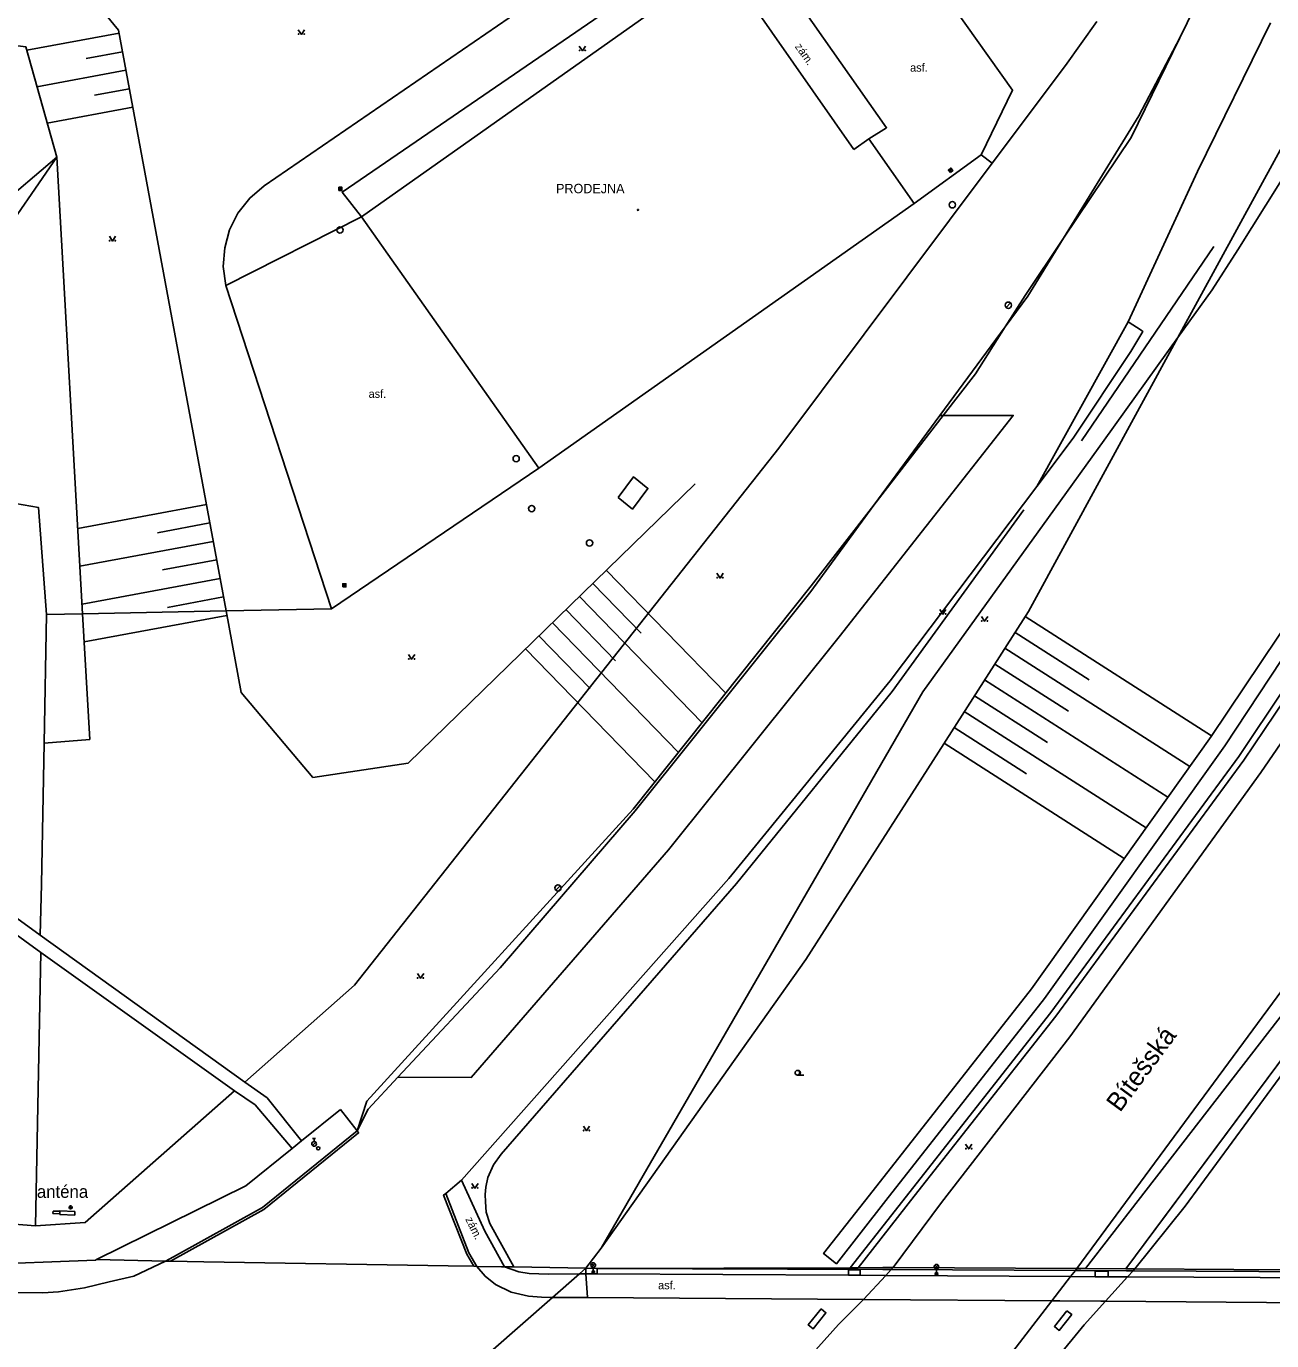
# Model space of a CAD drawing. Extents: x -602419 to -601554, y -1162937 to -1162362.
# Drawn here: x -601838.6 to -601739.3, y -1162718.7 to -1162613.9 of the extents above; entities that cross this region are included whole.
import ezdxf

# ---------------------------------------------------------------- set-up
doc = ezdxf.new("R2010")
doc.units = 0
doc.layers.add('Podklad', color=7, linetype='Continuous')

msp = doc.modelspace()

# ---------------------------------------------------------------- linework, layer by layer
at = {"layer": 'Podklad'}
for p, q in [((-601764.9776, -1162625.4581), (-601764.7824, -1162625.3019)), ((-601813.675, -1162626.86), (-601813.425, -1162626.86)), ((-601760.447, -1162636.3165), (-601760.0935, -1162635.963)), ((-601813.365, -1162658.48), (-601813.115, -1162658.48)), ((-601796.377, -1162682.7965), (-601796.0235, -1162682.443)), ((-601777.1, -1162697.5475), (-601776.6, -1162697.5475)), ((-601815.779, -1162703.176), (-601815.514, -1162702.911)), ((-601815.775, -1162702.6025), (-601815.525, -1162702.6025)), ((-601815.65, -1162702.8525), (-601815.65, -1162702.6025)), ((-601793.5125, -1162712.84), (-601793.2475, -1162712.575)), ((-601793.5125, -1162712.575), (-601793.2475, -1162712.84)), ((-601793.38, -1162712.895), (-601793.38, -1162713.27)), ((-601766.1425, -1162712.97), (-601765.8775, -1162712.705)), ((-601766.1425, -1162712.705), (-601765.8775, -1162712.97)), ((-601766.01, -1162713.025), (-601766.01, -1162713.4))]:
    msp.add_line(p, q, dxfattribs=at)
for points in [[(-601808.15, -1162672.6599), (-601815.75, -1162673.8), (-601821.46, -1162667.02), (-601822.6642, -1162660.5227), (-601831.25, -1162614.2), (-601835.42, -1162609.1), (-601841.14, -1162606.25), (-601856.39, -1162605.09), (-601882.54, -1162586.09)], [(-601811.44, -1162699.63), (-601790.2, -1162676.34), (-601776.01, -1162658.53), (-601771.0161, -1162652.0886), (-601765.466, -1162644.9297), (-601762.9, -1162641.62), (-601760.5218, -1162637.8699), (-601758.93, -1162635.36), (-601755.8662, -1162630.788), (-601750.48, -1162622.75), (-601746.602, -1162614.8054), (-601737.73, -1162596.63)], [(-601767.78, -1162628.02), (-601762.44, -1162624.15), (-601759.94, -1162619), (-601772.06, -1162601.92)], [(-601785.2, -1162602.9699), (-601819.62, -1162626.61)], [(-601884.69, -1162606.27), (-601871.19, -1162607.53), (-601858.53, -1162613.06), (-601840.5739, -1162615.291), (-601838.65, -1162615.53), (-601836.18, -1162624.34)], [(-601811.86, -1162629.08), (-601813.4099, -1162627.12), (-601783.04, -1162606.31)], [(-601780.9099, -1162606.4099), (-601769.99, -1162621.98), (-601771.4, -1162622.88)], [(-601811.86, -1162629.08), (-601781.92, -1162607.94)], [(-601780.69, -1162612.1599), (-601772.59, -1162623.71)], [(-601816.9099, -1162614.165), (-601816.6599, -1162614.54), (-601816.4099, -1162614.165)], [(-601803.88, -1162705.94), (-601782.56, -1162681.86), (-601769.7, -1162666.09), (-601758, -1162650.59), (-601755.1, -1162646.75), (-601750.51, -1162639.84), (-601749.54, -1162638.24), (-601749.69, -1162638.14), (-601750.71, -1162637.46), (-601745.19, -1162625.47), (-601739.36, -1162613.62)], [(-601761.56, -1162624.8199), (-601755.72, -1162617.0199), (-601753.21, -1162613.52)], [(-601831.2, -1162614.45), (-601838.57, -1162615.81)], [(-601794.5, -1162615.465), (-601794.25, -1162615.84), (-601794, -1162615.465)], [(-601771.0161, -1162652.0886), (-601765.732, -1162644.93), (-601760.5218, -1162637.8699), (-601758.717, -1162635.4249), (-601755.8662, -1162630.788), (-601749.8638, -1162621.0248), (-601746.602, -1162614.8054)], [(-601746.75, -1162638.71), (-601734.06, -1162615.46)], [(-601830.93, -1162615.92), (-601833.82, -1162616.46)], [(-601757.4, -1162691.44), (-601770.04, -1162707.55), (-601773.99, -1162712.59), (-601775.01, -1162711.79), (-601771.06, -1162706.75), (-601758.44, -1162690.6599), (-601744.1, -1162670.55), (-601729.44, -1162648.7), (-601716.39, -1162627.23), (-601716.71, -1162624), (-601732.24, -1162616.35)], [(-601746.75, -1162638.71), (-601744.01, -1162634.91), (-601741.98, -1162631.71), (-601738.61, -1162626.39), (-601734.96, -1162620.65), (-601732.34, -1162616.52), (-601732.24, -1162616.35)], [(-601830.6599, -1162617.4), (-601837.76, -1162618.71)], [(-601830.38, -1162618.87), (-601833.17, -1162619.39)], [(-601830.11, -1162620.35), (-601836.94, -1162621.61)], [(-601772.59, -1162623.71), (-601771.4, -1162622.88)], [(-601771.4, -1162622.88), (-601767.78, -1162628.02)], [(-601836.18, -1162624.34), (-601841.0524, -1162631.4107), (-601845.8, -1162638.3), (-601865.86, -1162636.4)], [(-601836.18, -1162624.34), (-601841.0118, -1162628.4378), (-601848.1599, -1162634.5), (-601865.49, -1162632.86)], [(-601836.18, -1162624.34), (-601834.111, -1162660.7441), (-601833.54, -1162670.79)], [(-601821.168, -1162698.102), (-601812.43, -1162690.3699), (-601778.57, -1162647.5299), (-601761.56, -1162624.8199)], [(-601761.56, -1162624.8199), (-601762.44, -1162624.15)], [(-601819.62, -1162626.61), (-601820.78, -1162627.6), (-601821.73, -1162628.79), (-601822.4, -1162630.12), (-601822.78, -1162631.56), (-601822.89, -1162633.04), (-601822.68, -1162634.58)], [(-601754.81, -1162712.98), (-601750.93, -1162707.7199), (-601730.62, -1162680.1599), (-601712.05, -1162651.99), (-601703.56, -1162637.96), (-601697.14, -1162626.52)], [(-601767.78, -1162628.02), (-601797.73, -1162649.15)], [(-601811.86, -1162629.08), (-601822.68, -1162634.58)], [(-601797.73, -1162649.15), (-601811.86, -1162629.08)], [(-601716.64, -1162629.79), (-601728.48, -1162649.29), (-601743.02, -1162671.28), (-601757.4, -1162691.44)], [(-601831.98, -1162630.645), (-601831.73, -1162631.02), (-601831.48, -1162630.645)], [(-601772.89, -1162712.9099), (-601756.9, -1162692.56), (-601741.89, -1162672.13), (-601727.1599, -1162650.1), (-601721.39, -1162640.75), (-601715.45, -1162630.9)], [(-601714.93, -1162631.2199), (-601720.98, -1162641.02), (-601726.65, -1162650.42), (-601741.48, -1162672.42), (-601756.5, -1162692.86), (-601767.78, -1162707.21), (-601772.25, -1162712.9099)], [(-601754.43, -1162646.96), (-601743.88, -1162631.45)], [(-601822.68, -1162634.58), (-601814.27, -1162660.36), (-601797.73, -1162649.15)], [(-601758, -1162650.59), (-601750.71, -1162637.46)], [(-601793.98, -1162712.96), (-601792.76, -1162711.36), (-601789.4, -1162705.55), (-601779.84, -1162689.02), (-601774.55, -1162679.88), (-601767.1, -1162666.99), (-601757.08, -1162653.06), (-601752.64, -1162646.9), (-601746.75, -1162638.71)], [(-601793.98, -1162712.96), (-601792.76, -1162711.36), (-601789.4, -1162705.55), (-601779.84, -1162689.02), (-601774.55, -1162679.88), (-601767.1, -1162666.99), (-601757.08, -1162653.06), (-601752.64, -1162646.9), (-601746.75, -1162638.71)], [(-601792.76, -1162711.36), (-601776.44, -1162688.33), (-601758.67, -1162660.56), (-601746.75, -1162638.71)], [(-601765.732, -1162644.93), (-601765.466, -1162644.9297), (-601759.891, -1162644.924), (-601773.759, -1162662.6), (-601787.369, -1162679.592), (-601803.119, -1162697.739), (-601808.958, -1162697.726), (-601811.331, -1162700.27), (-601812.2199, -1162702)], [(-601791.4099, -1162651.48), (-601790.18, -1162649.84), (-601789.03, -1162650.75), (-601790.26, -1162652.4), (-601791.4099, -1162651.48)], [(-601808.15, -1162672.6599), (-601785.26, -1162650.4)], [(-601836.99, -1162660.7999), (-601837.63, -1162652.2799), (-601841.33, -1162651.6499)], [(-601824.24, -1162652.04), (-601834.5, -1162653.94)], [(-601808.958, -1162697.726), (-601800.81, -1162688.99), (-601790.031, -1162676.477), (-601776.028, -1162658.975), (-601771.0161, -1162652.0886)], [(-601800.73, -1162703.85), (-601781.96, -1162682.27), (-601769.54, -1162666.94), (-601759.04, -1162652.4699)], [(-601823.96, -1162653.51), (-601828.14, -1162654.29)], [(-601823.69, -1162654.99), (-601834.33, -1162656.96)], [(-601823.42, -1162656.46), (-601827.75, -1162657.26)], [(-601792.34, -1162657.29), (-601782.82, -1162667.08)], [(-601711.36, -1162657), (-601711.57, -1162657.34), (-601720.41, -1162670.93), (-601728.96, -1162683.45), (-601736.3, -1162693.37), (-601750.9, -1162713)], [(-601711.03, -1162657.22), (-601727.42, -1162682.48), (-601746.1599, -1162708), (-601750.2, -1162713.01)], [(-601823.14, -1162657.94), (-601834.15, -1162659.98)], [(-601793.42, -1162658.33), (-601789.55, -1162662.3)], [(-601783.52, -1162657.525), (-601783.27, -1162657.9), (-601783.02, -1162657.525)], [(-601822.87, -1162659.4099), (-601827.35, -1162660.24)], [(-601794.49, -1162659.38), (-601784.7, -1162669.44)], [(-601836.99, -1162660.7999), (-601834.111, -1162660.7441), (-601822.6642, -1162660.5227), (-601814.27, -1162660.36)], [(-601795.57, -1162660.42), (-601791.6, -1162664.5)], [(-601765.75, -1162660.415), (-601765.5, -1162660.79), (-601765.25, -1162660.415)], [(-601837.505, -1162686.3819), (-601837.38, -1162682.3199), (-601837.18, -1162671.08), (-601836.99, -1162660.7999)], [(-601822.6, -1162660.89), (-601833.98, -1162663)], [(-601796.64, -1162661.4699), (-601786.59, -1162671.81)], [(-601762.42, -1162660.975), (-601762.17, -1162661.35), (-601761.92, -1162660.975)], [(-601758.93, -1162660.9699), (-601744.06, -1162670.49)], [(-601797.7199, -1162662.51), (-601793.64, -1162666.7)], [(-601759.74, -1162662.24), (-601753.82, -1162666.03)], [(-601798.79, -1162663.56), (-601788.4699, -1162674.17)], [(-601732.77, -1162662.68), (-601740.14, -1162673.42), (-601755.36, -1162694.5), (-601765.62, -1162707.71), (-601769.46, -1162712.9)], [(-601760.55, -1162663.5), (-601745.8, -1162672.94)], [(-601808.12, -1162664.005), (-601807.87, -1162664.38), (-601807.62, -1162664.005)], [(-601761.36, -1162664.76), (-601755.49, -1162668.52)], [(-601762.17, -1162666.03), (-601747.55, -1162675.38)], [(-601762.98, -1162667.29), (-601757.15, -1162671.02)], [(-601763.79, -1162668.55), (-601749.29, -1162677.83)], [(-601764.59, -1162669.82), (-601758.82, -1162673.51)], [(-601833.54, -1162670.79), (-601837.18, -1162671.08)], [(-601765.4, -1162671.08), (-601751.03, -1162680.27)], [(-601837.505, -1162686.3819), (-601844.6636, -1162681.1796)], [(-601845.52, -1162681.89), (-601837.447, -1162687.771)], [(-601821.168, -1162698.102), (-601837.505, -1162686.3819)], [(-601837.87, -1162709.5599), (-601837.447, -1162687.771)], [(-601837.447, -1162687.771), (-601821.9889, -1162698.7944)], [(-601807.4099, -1162689.455), (-601807.1599, -1162689.83), (-601806.9099, -1162689.455)], [(-601754.11, -1162712.98), (-601749.9099, -1162707.55), (-601738.15, -1162692.33)], [(-601750.9, -1162713), (-601736.3, -1162693.37), (-601747.21, -1162708.04), (-601750.9, -1162713)], [(-601816.65, -1162702.7894), (-601819.403, -1162699.3569), (-601821.168, -1162698.102)], [(-601837.87, -1162709.5599), (-601833.92, -1162709.3099), (-601821.9889, -1162698.7944)], [(-601821.9889, -1162698.7944), (-601820.35, -1162699.9219), (-601817.4019, -1162703.3961)], [(-601833, -1162712.25), (-601821.1, -1162706.38), (-601817.4019, -1162703.3961), (-601816.65, -1162702.7894), (-601813.54, -1162700.28)], [(-601812.2199, -1162702), (-601813.54, -1162700.28)], [(-601811.44, -1162699.63), (-601812.2199, -1162702)], [(-601827.51, -1162712.39), (-601826.87, -1162712.04), (-601819.76, -1162708.11), (-601812.2199, -1162702)], [(-601812.2199, -1162702), (-601812.1, -1162702.16), (-601819.65, -1162708.28), (-601827.1, -1162712.4)], [(-601812.2199, -1162702), (-601812.1, -1162702.16), (-601819.65, -1162708.28), (-601827.1, -1162712.4)], [(-601794.17, -1162701.615), (-601793.92, -1162701.99), (-601793.67, -1162701.615)], [(-601763.68, -1162703.065), (-601763.43, -1162703.44), (-601763.18, -1162703.065)], [(-601801.63, -1162709.39), (-601801.93, -1162708.4699), (-601801.99, -1162707.67), (-601802.01, -1162707.06), (-601801.96, -1162706.49), (-601801.8, -1162705.73), (-601801.34, -1162704.71), (-601800.73, -1162703.85)], [(-601805.15, -1162706.98), (-601803.88, -1162705.94)], [(-601803.88, -1162705.94), (-601802.04, -1162709.99), (-601800.4699, -1162712.84)], [(-601803.07, -1162706.195), (-601802.82, -1162706.57), (-601802.57, -1162706.195)], [(-601802.8977, -1162712.8038), (-601802.9012, -1162712.7978), (-601803.48, -1162711.8199), (-601805.32, -1162707.1199), (-601805.15, -1162706.98)], [(-601802.66, -1162712.81), (-601803.3, -1162711.73), (-601805.15, -1162706.98)], [(-601802.66, -1162712.81), (-601803.3, -1162711.73), (-601805.15, -1162706.98)], [(-601793.06, -1162712.9699), (-601770.29, -1162713.06), (-601769.6129, -1162713.063), (-601754.924, -1162713.1279), (-601754.49, -1162713.13), (-601750.84, -1162713.15), (-601750.33, -1162713.1529), (-601735.26, -1162713.25), (-601734.5248, -1162713.2571), (-601729.38, -1162713.29), (-601712.7389, -1162713.471), (-601711.79, -1162713.48), (-601711.7578, -1162713.479), (-601705.93, -1162713.2499), (-601703.86, -1162711.1599), (-601703.5312, -1162710.8299), (-601703.3531, -1162710.6501), (-601699.8106, -1162707.0725)], [(-601793.06, -1162712.9699), (-601770.29, -1162713.06), (-601769.6129, -1162713.063), (-601754.924, -1162713.1279), (-601754.49, -1162713.13), (-601750.84, -1162713.15), (-601750.33, -1162713.1529), (-601735.26, -1162713.25), (-601734.5248, -1162713.2571), (-601729.38, -1162713.29), (-601712.7389, -1162713.471), (-601711.79, -1162713.48), (-601711.7578, -1162713.479), (-601705.93, -1162713.2499), (-601703.86, -1162711.1599), (-601703.5312, -1162710.8299), (-601703.3531, -1162710.6501), (-601699.8106, -1162707.0725)], [(-601859.37, -1162707.86), (-601837.87, -1162709.56)], [(-601836.47, -1162708.39), (-601836.48, -1162708.6)], [(-601836.48, -1162708.6), (-601835.93, -1162708.62)], [(-601835.93, -1162708.41), (-601836.47, -1162708.39)], [(-601834.74, -1162708.42), (-601835.93, -1162708.38)], [(-601835.93, -1162708.38), (-601835.93, -1162708.41), (-601835.93, -1162708.62), (-601835.93, -1162708.67)], [(-601835.93, -1162708.67), (-601834.74, -1162708.71)], [(-601834.74, -1162708.71), (-601834.74, -1162708.42)], [(-601912.49, -1162708.95), (-601899.4699, -1162709.24), (-601886.33, -1162712.36), (-601842.86, -1162712.69), (-601833.09, -1162712.3)], [(-601912.49, -1162708.95), (-601899.4699, -1162709.24), (-601886.33, -1162712.36), (-601842.86, -1162712.69), (-601833.09, -1162712.3)], [(-601799.7199, -1162712.85), (-601801.63, -1162709.39)], [(-601837.28, -1162714.9099), (-601836.03, -1162714.83), (-601833.95, -1162714.51), (-601831.99, -1162714.05), (-601830.03, -1162713.59), (-601827.51, -1162712.39)], [(-601837.28, -1162714.9099), (-601836.03, -1162714.83), (-601833.95, -1162714.51), (-601831.99, -1162714.05), (-601830.03, -1162713.59), (-601827.51, -1162712.39)], [(-601833.09, -1162712.3), (-601833, -1162712.25)], [(-601833.09, -1162712.3), (-601833, -1162712.25)], [(-601833, -1162712.25), (-601827.51, -1162712.39), (-601827.1, -1162712.4), (-601824.45, -1162712.44), (-601804.95, -1162712.77), (-601802.9, -1162712.8), (-601802.66, -1162712.81), (-601800.7, -1162712.84), (-601800.47, -1162712.84), (-601799.33, -1162713.25), (-601798.5, -1162713.37), (-601796.94, -1162713.43), (-601794.49, -1162713.41), (-601794.22, -1162713.4)], [(-601833, -1162712.25), (-601827.51, -1162712.39), (-601827.1, -1162712.4), (-601824.45, -1162712.44), (-601804.95, -1162712.77), (-601802.9, -1162712.8), (-601802.66, -1162712.81), (-601800.7, -1162712.84), (-601800.47, -1162712.84), (-601799.33, -1162713.25), (-601798.5, -1162713.37), (-601796.94, -1162713.43), (-601794.49, -1162713.41), (-601794.22, -1162713.4)], [(-601793.98, -1162712.96), (-601794.4894, -1162713.4059), (-601796.6372, -1162715.2857), (-601811.4818, -1162728.2775)], [(-601796.49, -1162715.29), (-601796.6372, -1162715.2857), (-601797.52, -1162715.26), (-601798.55, -1162715.18), (-601799.92, -1162714.86), (-601801.18, -1162714.24), (-601802.01, -1162713.59), (-601802.66, -1162712.81)], [(-601799.7199, -1162712.85), (-601800.4699, -1162712.84)], [(-601793.98, -1162712.96), (-601799.7199, -1162712.85)], [(-601793.98, -1162712.96), (-601799.7199, -1162712.85)], [(-601793.06, -1162712.9699), (-601793.98, -1162712.96)], [(-601793.98, -1162713.4), (-601793.98, -1162712.96)], [(-601793.06, -1162712.9699), (-601793.98, -1162712.96)], [(-601772.89, -1162712.9099), (-601793.06, -1162712.9699)], [(-601793.06, -1162712.9699), (-601793.06, -1162713.2199)], [(-601793.06, -1162712.9699), (-601793.06, -1162713.2199)], [(-601772.25, -1162712.9099), (-601772.89, -1162712.9099)], [(-601770.28, -1162712.9), (-601772.25, -1162712.9099)], [(-601771.84, -1162715.44), (-601770.0496, -1162713.5292), (-601769.6129, -1162713.063), (-601769.46, -1162712.9)], [(-601771.84, -1162715.44), (-601770.0496, -1162713.5292), (-601769.6129, -1162713.063), (-601769.46, -1162712.9)], [(-601769.46, -1162712.9), (-601770.28, -1162712.9)], [(-601754.81, -1162712.98), (-601769.46, -1162712.9)], [(-601756.8, -1162715.56), (-601755.3069, -1162713.6181), (-601754.924, -1162713.1279), (-601754.81, -1162712.98)], [(-601756.8, -1162715.56), (-601755.3069, -1162713.6181), (-601754.924, -1162713.1279), (-601754.81, -1162712.98)], [(-601754.11, -1162712.98), (-601754.81, -1162712.98)], [(-601750.9, -1162713), (-601754.11, -1162712.98)], [(-601750.2, -1162713.01), (-601750.9, -1162713)], [(-601793.98, -1162713.4), (-601794.2201, -1162713.4028)], [(-601793.85, -1162715.28), (-601793.98, -1162713.4)], [(-601793.06, -1162713.4), (-601793.98, -1162713.4)], [(-601793.06, -1162713.2199), (-601793.06, -1162713.4)], [(-601793.06, -1162713.4), (-601773.02, -1162713.52)], [(-601773.02, -1162713.09), (-601772.09, -1162713.09), (-601772.09, -1162713.52), (-601773.02, -1162713.52), (-601773.02, -1162713.34), (-601773.02, -1162713.09)], [(-601772.09, -1162713.52), (-601770.0496, -1162713.5292), (-601755.3021, -1162713.6181), (-601753.34, -1162713.63)], [(-601753.34, -1162713.45), (-601753.34, -1162713.2), (-601752.32, -1162713.21), (-601752.32, -1162713.46), (-601752.32, -1162713.64), (-601753.34, -1162713.63), (-601753.34, -1162713.45)], [(-601752.54, -1162715.58), (-601750.7801, -1162713.6472), (-601750.33, -1162713.1529), (-601750.2, -1162713.01)], [(-601752.54, -1162715.58), (-601750.7801, -1162713.6472), (-601750.33, -1162713.1529), (-601750.2, -1162713.01)], [(-601752.32, -1162713.64), (-601750.7801, -1162713.6472), (-601734.91, -1162713.7329), (-601734.902, -1162713.7329), (-601733.6599, -1162713.74)], [(-601734.4, -1162713.1), (-601750.2, -1162713.01)], [(-601844.3, -1162714.84), (-601840.33, -1162714.88), (-601837.28, -1162714.9099)], [(-601796.49, -1162715.29), (-601793.85, -1162715.28)], [(-601793.85, -1162715.28), (-601771.84, -1162715.44)], [(-601785.71, -1162730.7199), (-601773.83, -1162717.43), (-601771.84, -1162715.44)], [(-601771.84, -1162715.44), (-601756.8, -1162715.56)], [(-601768.78, -1162730.81), (-601767.31, -1162729.19), (-601756.8, -1162715.56)], [(-601765.17, -1162730.83), (-601754.24, -1162717.46), (-601752.54, -1162715.58)], [(-601756.8, -1162715.56), (-601756.17, -1162715.56), (-601752.89, -1162715.58), (-601752.54, -1162715.58)], [(-601752.54, -1162715.58), (-601736.4699, -1162715.71)], [(-601775.21, -1162716.2), (-601774.82, -1162716.51), (-601775.84, -1162717.78), (-601776.23, -1162717.4699), (-601775.21, -1162716.2)], [(-601755.61, -1162716.34), (-601755.2199, -1162716.65), (-601756.21, -1162717.9099), (-601756.6, -1162717.59), (-601755.61, -1162716.34)]]:
    msp.add_lwpolyline(points, dxfattribs=at)
for points in [[(-601764.8996, -1162625.5557), (-601764.7043, -1162625.3996), (-601764.8604, -1162625.2043), (-601765.0557, -1162625.3604)], [(-601813.675, -1162626.985), (-601813.425, -1162626.985), (-601813.425, -1162626.735), (-601813.675, -1162626.735)], [(-601813.365, -1162658.605), (-601813.115, -1162658.605), (-601813.115, -1162658.355), (-601813.365, -1162658.355)]]:
    msp.add_lwpolyline(points, close=True, dxfattribs=at)
for centre, radius in [((-601816.885, -1162614.5149), 0.025), ((-601816.4353, -1162614.5149), 0.025), ((-601794.4751, -1162615.8149), 0.025), ((-601794.0254, -1162615.8149), 0.025), ((-601764.74, -1162628.13), 0.25), ((-601789.81, -1162628.54), 0.045), ((-601789.81, -1162628.54), 0.0199), ((-601813.59, -1162630.14), 0.25), ((-601831.9551, -1162630.9949), 0.025), ((-601831.5054, -1162630.9949), 0.025), ((-601760.27, -1162636.14), 0.25), ((-601799.53, -1162648.38), 0.25), ((-601798.29, -1162652.36), 0.25), ((-601793.68, -1162655.1), 0.25), ((-601783.4951, -1162657.8749), 0.025), ((-601783.0454, -1162657.8749), 0.025), ((-601765.7251, -1162660.7649), 0.025), ((-601765.2754, -1162660.7649), 0.025), ((-601762.3951, -1162661.3249), 0.025), ((-601761.9454, -1162661.3249), 0.025), ((-601808.0951, -1162664.3549), 0.025), ((-601807.6454, -1162664.3549), 0.025), ((-601796.2, -1162682.62), 0.25), ((-601807.385, -1162689.8049), 0.025), ((-601806.9353, -1162689.8049), 0.025), ((-601777.1, -1162697.3598), 0.1875), ((-601794.1451, -1162701.9649), 0.025), ((-601793.6954, -1162701.9649), 0.025), ((-601815.65, -1162703.04), 0.1875), ((-601815.32, -1162703.39), 0.125), ((-601763.6551, -1162703.4149), 0.025), ((-601763.2054, -1162703.4149), 0.025), ((-601803.0451, -1162706.5449), 0.025), ((-601802.5954, -1162706.5449), 0.025), ((-601835.07, -1162708.1), 0.125), ((-601835.07, -1162708.1), 0.0152), ((-601793.38, -1162712.7075), 0.1875), ((-601766.01, -1162712.8375), 0.1875), ((-601793.38, -1162713.27), 0.1), ((-601793.38, -1162713.27), 0.0723), ((-601793.38, -1162713.27), 0.0438), ((-601766.01, -1162713.4), 0.1), ((-601766.01, -1162713.4), 0.0723), ((-601766.01, -1162713.4), 0.0438)]:
    msp.add_circle(centre, radius, dxfattribs=at)
msp.add_arc((-601777.0375, -1162697.3598), 0.1875, 260.405931, 99.594069, dxfattribs=at)

# ---------------------------------------------------------------- texts
for s, height, rotation, p in [(' zám.', 0.65, 305.04, (-601777.4699, -1162615.32)), ('Bítešská', 1.5, 53.58, (-601751.37, -1162700.58)), (' zám.', 0.65, 296.3, (-601803.71, -1162708.83))]:
    msp.add_text(s, height=height, rotation=rotation, dxfattribs=at).set_placement(p)
for s, height, p in [('asf.', 0.65, (-601768.11, -1162617.51)), ('PRODEJNA', 0.75, (-601796.35, -1162627.21)), ('asf.', 0.65, (-601811.3, -1162643.53)), ('anténa', 0.99995, (-601837.76, -1162707.34)), ('asf.', 0.65, (-601788.21, -1162714.63))]:
    msp.add_text(s, height=height, dxfattribs=at).set_placement(p)

doc.saveas('drawing.dxf')
